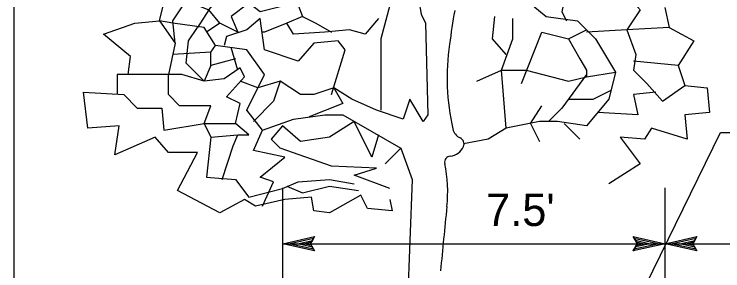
# Model space of a CAD drawing. Extents: x -119017 to -116080, y -104449 to -102845.
# Drawn here: x -118744.8 to -118613.8, y -103078.8 to -103031.3 of the extents above; entities that cross this region are included whole.
import ezdxf

# ---------------------------------------------------------------- set-up
doc = ezdxf.new("R2010")
doc.units = 0
for name, color, linetype in [('G-MARK', 7, 'Continuous'), ('G-TEXT', 7, 'Continuous'), ('Misc CnstDet(22)', 7, 'Continuous')]:
    doc.layers.add(name, color=color, linetype=linetype)

msp = doc.modelspace()

# ---------------------------------------------------------------- linework, layer by layer
at = {"layer": 'G-MARK'}
for p, q in [((-118695.17, -103118.46), (-118695.17, -103063.48)), ((-118624.48, -103121.36), (-118624.48, -103063.48)), ((-118695.17, -103073.82), (-118624.48, -103073.82)), ((-118624.48, -103073.82), (-118229.29, -103073.82))]:
    msp.add_line(p, q, dxfattribs=at)
msp.add_lwpolyline([(-118641.89, -103109.89), (-118614.2, -103053.25), (-118603.86, -103053.25)], dxfattribs=at)
at = {"layer": 'G-TEXT'}
for points in [[(-118689.27, -103075.14), (-118695.17, -103073.82), (-118689.27, -103072.51), (-118689.48, -103072.86), (-118693.8, -103073.82), (-118689.47, -103074.79), (-118689.68, -103074.44), (-118692.45, -103073.82), (-118689.69, -103073.21), (-118689.9, -103073.56), (-118691.09, -103073.82), (-118689.89, -103074.09), (-118690.05, -103073.82), (-118689.27, -103072.51), (-118690.05, -103073.82)], [(-118630.39, -103072.5), (-118624.48, -103073.82), (-118630.39, -103075.13), (-118630.18, -103074.78), (-118625.85, -103073.82), (-118630.18, -103072.85), (-118629.97, -103073.2), (-118627.2, -103073.82), (-118629.97, -103074.43), (-118629.76, -103074.08), (-118628.56, -103073.82), (-118629.76, -103073.55), (-118629.6, -103073.82), (-118630.39, -103075.13), (-118629.6, -103073.82)], [(-118618.58, -103075.14), (-118624.48, -103073.82), (-118618.58, -103072.51), (-118618.79, -103072.86), (-118623.11, -103073.82), (-118618.79, -103074.79), (-118618.99, -103074.44), (-118621.76, -103073.82), (-118619, -103073.21), (-118619.21, -103073.56), (-118620.4, -103073.82), (-118619.2, -103074.09), (-118619.36, -103073.82), (-118618.58, -103072.51), (-118619.36, -103073.82)]]:
    msp.add_lwpolyline(points, close=True, dxfattribs=at)
at = {"layer": 'Misc CnstDet(22)'}
for p, q in [((-118744.83, -103240.93), (-118744.83, -102917.66)), ((-118682.4, -103047.05), (-118685.71, -103044.99)), ((-118685.71, -103044.99), (-118684.06, -103047.88)), ((-118684.06, -103047.88), (-118690.26, -103050.36)), ((-118673.31, -103056.15), (-118676.2, -103059.04)), ((-118624.48, -103121.36), (-118624.48, -103063.48)), ((-118624.48, -103073.82), (-118624.48, -103073.82))]:
    msp.add_line(p, q, dxfattribs=at)
for points in [[(-118639.83, -102986.28), (-118643.13, -102993.73), (-118637.76, -102992.9), (-118634.87, -103000.75), (-118629.9, -103001.99), (-118627.84, -103001.58), (-118628.25, -103008.19), (-118634.45, -103006.95), (-118630.32, -103012.33), (-118631.15, -103013.98), (-118628.25, -103014.39), (-118630.73, -103018.53), (-118632.8, -103021.84), (-118635.69, -103025.97), (-118631.97, -103027.21), (-118629.08, -103030.52), (-118631.56, -103034.24), (-118629.9, -103038.78), (-118630.32, -103041.68), (-118627.84, -103044.16), (-118624.94, -103047.47), (-118620.81, -103044.57)], [(-118706.79, -103033), (-118708.86, -103030.52), (-118704.73, -103025.56), (-118708.45, -103025.14), (-118707.21, -103020.18), (-118711.76, -103017.7), (-118710.1, -103012.74), (-118706.38, -103009.85), (-118706.79, -103004.47), (-118706.38, -103001.17), (-118711.34, -103003.23), (-118714.24, -103002.41), (-118715.89, -103003.23), (-118713, -103006.13), (-118714.65, -103010.26), (-118718.78, -103012.33)], [(-118683.65, -103017.7), (-118674.96, -103023.49), (-118672.48, -103025.97), (-118670, -103028.86), (-118669.59, -103031.34), (-118668.76, -103033), (-118668.35, -103049.95), (-118669.18, -103051.19), (-118671.66, -103047.05), (-118672.9, -103050.77), (-118677.86, -103049.12), (-118682.4, -103047.05)], [(-118651.4, -103027.62), (-118646.44, -103031.76), (-118640.65, -103032.58), (-118637.35, -103035.89), (-118633.63, -103042.09), (-118634.87, -103047.05), (-118639, -103052.01), (-118644.37, -103051.19), (-118647.68, -103051.19), (-118653.88, -103052.43), (-118657.19, -103054.49), (-118661.74, -103055.32)], [(-118715.06, -103036.72), (-118715.48, -103032.58), (-118713, -103028.86), (-118708.86, -103030.52), (-118710.93, -103033.82)], [(-118674.96, -103028.04), (-118677.03, -103035.89), (-118677.03, -103044.57), (-118677.03, -103049.12)], [(-118643.13, -103028.86), (-118643.55, -103030.93), (-118642.72, -103032.58)], [(-118717.96, -103032.58), (-118717.13, -103029.28)], [(-118685.71, -103029.28), (-118694.39, -103029.69), (-118699.35, -103030.93), (-118701.42, -103029.28), (-118704.73, -103031.76), (-118703.49, -103034.65)], [(-118692.33, -103029.69), (-118691.5, -103031.76), (-118689.02, -103033), (-118686.13, -103034.65)], [(-118624.53, -103030.1), (-118623.7, -103033.82), (-118619.16, -103036.3), (-118622.05, -103040.85), (-118620.81, -103044.57), (-118616.68, -103044.99), (-118616.26, -103049.53), (-118620.81, -103049.95), (-118620.4, -103054.49), (-118627.01, -103052.43), (-118628.25, -103054.49), (-118632.8, -103054.08), (-118629.08, -103059.04), (-118634.87, -103062.76)], [(-118691.5, -103031.76), (-118694.39, -103033)], [(-118653.88, -103038.78), (-118656.36, -103035.89), (-118655.95, -103031.76)], [(-118723.74, -103042.5), (-118723.33, -103039.2), (-118728.29, -103035.06), (-118722.5, -103033), (-118717.96, -103032.58), (-118715.06, -103036.72), (-118716.3, -103042.5)], [(-118698.94, -103052.84), (-118701.83, -103049.12), (-118698.53, -103042.5), (-118701.83, -103037.96), (-118707.62, -103037.13), (-118709.69, -103033.82), (-118715.48, -103033), (-118717.96, -103032.58)], [(-118703.49, -103034.65), (-118706.79, -103033), (-118709.27, -103034.65)], [(-118686.13, -103046.23), (-118683.65, -103037.96), (-118684.89, -103036.3), (-118689.43, -103036.72), (-118692.33, -103040.02), (-118698.53, -103037.96), (-118699.35, -103032.17), (-118701.83, -103034.24), (-118705.55, -103035.48), (-118705.97, -103037.13)], [(-118677.44, -103032.17), (-118679.92, -103035.06), (-118682.82, -103034.24), (-118687.37, -103034.65), (-118693.15, -103035.06), (-118694.39, -103033), (-118698.53, -103034.65), (-118698.94, -103034.65)], [(-118653.88, -103052.43), (-118654.71, -103041.68), (-118652.64, -103035.89), (-118652.64, -103032.17)], [(-118709.69, -103043.74), (-118713, -103040.44), (-118712.58, -103036.3), (-118710.93, -103033.82)], [(-118642.31, -103035.89), (-118639, -103034.24)], [(-118631.56, -103034.24), (-118639, -103034.65)], [(-118623.7, -103033.82), (-118631.56, -103034.24)], [(-118650.99, -103044.16), (-118647.27, -103034.65), (-118642.31, -103035.89), (-118640.24, -103039.61), (-118639, -103041.68), (-118639, -103042.92)], [(-118708.45, -103040.85), (-118708.45, -103038.37), (-118707.62, -103037.13)], [(-118703.49, -103041.68), (-118704.73, -103037.54)], [(-118708.45, -103038.37), (-118715.48, -103038.78)], [(-118703.9, -103039.61), (-118708.45, -103040.85), (-118709.69, -103043.74)], [(-118622.05, -103040.85), (-118630.32, -103040.02)], [(-118706.38, -103061.93), (-118704.31, -103055.73), (-118703.49, -103053.67), (-118701.42, -103053.67), (-118703.9, -103051.6), (-118703.07, -103047.88), (-118705.55, -103046.64), (-118702.25, -103042.92), (-118703.07, -103041.26), (-118705.97, -103043.33), (-118709.69, -103043.74), (-118713.82, -103042.5), (-118725.81, -103042.5), (-118725.81, -103046.23)], [(-118659.26, -103043.74), (-118654.71, -103041.68), (-118650.16, -103041.68), (-118642.31, -103043.74), (-118639, -103042.92), (-118633.63, -103042.09)], [(-118709.69, -103051.6), (-118708.45, -103048.29), (-118714.24, -103048.29), (-118716.3, -103046.23), (-118716.3, -103042.5)], [(-118639, -103042.5), (-118643.55, -103048.71), (-118646.03, -103051.19)], [(-118685.71, -103044.99), (-118689.43, -103046.23), (-118691.91, -103046.23), (-118695.63, -103043.74), (-118699.77, -103044.99), (-118703.07, -103043.74)], [(-118695.63, -103043.74), (-118696.87, -103047.47), (-118700.59, -103051.19)], [(-118675.38, -103065.65), (-118674.96, -103067.72), (-118679.51, -103067.31), (-118680.75, -103064.83), (-118686.54, -103068.13), (-118689.43, -103067.72), (-118689.85, -103065.24), (-118694.81, -103065.65), (-118700.18, -103066.89), (-118702.25, -103065.65), (-118706.79, -103068.13), (-118714.65, -103064), (-118710.93, -103056.97), (-118716.3, -103056.97), (-118718.78, -103054.08), (-118726.22, -103057.39), (-118725.4, -103052.01), (-118731.18, -103052.43), (-118732.01, -103045.81), (-118724.57, -103046.23), (-118722.09, -103048.71), (-118717.54, -103048.71), (-118717.13, -103052.84), (-118709.69, -103051.6), (-118708.45, -103054.08), (-118709.27, -103061.52), (-118703.9, -103061.93), (-118701.42, -103065.24), (-118695.22, -103063.59), (-118692.33, -103062.35), (-118686.54, -103061.93), (-118681.99, -103062.76)], [(-118642.31, -103047.05), (-118637.76, -103047.05), (-118634.45, -103045.4)], [(-118626.18, -103045.81), (-118630.32, -103046.23), (-118629.49, -103049.95), (-118636.93, -103049.53)], [(-118649.33, -103051.6), (-118647.27, -103048.29)], [(-118698.94, -103066.89), (-118696.87, -103062.35), (-118699.35, -103061.52), (-118694.81, -103057.8), (-118700.59, -103056.56), (-118698.94, -103052.84), (-118693.15, -103050.77), (-118687.37, -103049.95), (-118684.06, -103049.95)], [(-118684.06, -103049.95), (-118673.31, -103056.15), (-118671.24, -103061.93), (-118672.07, -103084.67), (-118671.66, -103091.28), (-118680.34, -103087.15), (-118677.03, -103091.28), (-118673.72, -103094.18), (-118672.48, -103099.14), (-118671.66, -103104.1), (-118671.66, -103110.71), (-118671.66, -103116.09), (-118672.07, -103116.91), (-118672.07, -103118.57), (-118674.14, -103121.46), (-118678.27, -103123.11)], [(-118677.44, -103053.67), (-118678.68, -103057.8), (-118681.99, -103051.19), (-118686.54, -103054.08), (-118691.91, -103054.91), (-118695.22, -103052.01), (-118697.29, -103054.49)], [(-118709.69, -103051.6), (-118703.9, -103051.6)], [(-118649.33, -103051.6), (-118647.68, -103054.91)], [(-118643.13, -103051.6), (-118640.24, -103054.49)], [(-118708.45, -103054.08), (-118703.49, -103053.67)], [(-118675.38, -103063.59), (-118681.99, -103061.11), (-118677.86, -103059.87), (-118686.13, -103059.45), (-118695.63, -103056.15), (-118697.29, -103054.49)], [(-118694.39, -103063.17), (-118691.5, -103064.41), (-118686.54, -103063.17), (-118681.16, -103064)]]:
    msp.add_lwpolyline(points, dxfattribs=at)
for centre, radius, start, end in [((-118355.22, -103081.69), 312.35, 170.5985, 171.7592), ((-118621.8, -103043.08), 42.98, 171.7592, 192.7808), ((-118661.38, -103052.06), 2.4, 192.7808, 245.4322), ((-118662.89, -103055.36), 1.24, 336.4965, 65.4322), ((-118664.45, -103054.69), 2.94, 274.8593, 336.4965), ((-118664.1, -103058.74), 1.13, 94.8593, 191.7919), ((-118690.45, -103064.24), 25.78, 353.9354, 11.7919), ((-117867.38, -103151.69), 801.92, 173.93543, 174.78846)]:
    msp.add_arc(centre, radius, start, end, dxfattribs=at)

# ---------------------------------------------------------------- texts
msp.add_text("7.5'", height=6, dxfattribs=at).set_placement((-118657.57, -103070.55))

doc.saveas('drawing.dxf')
